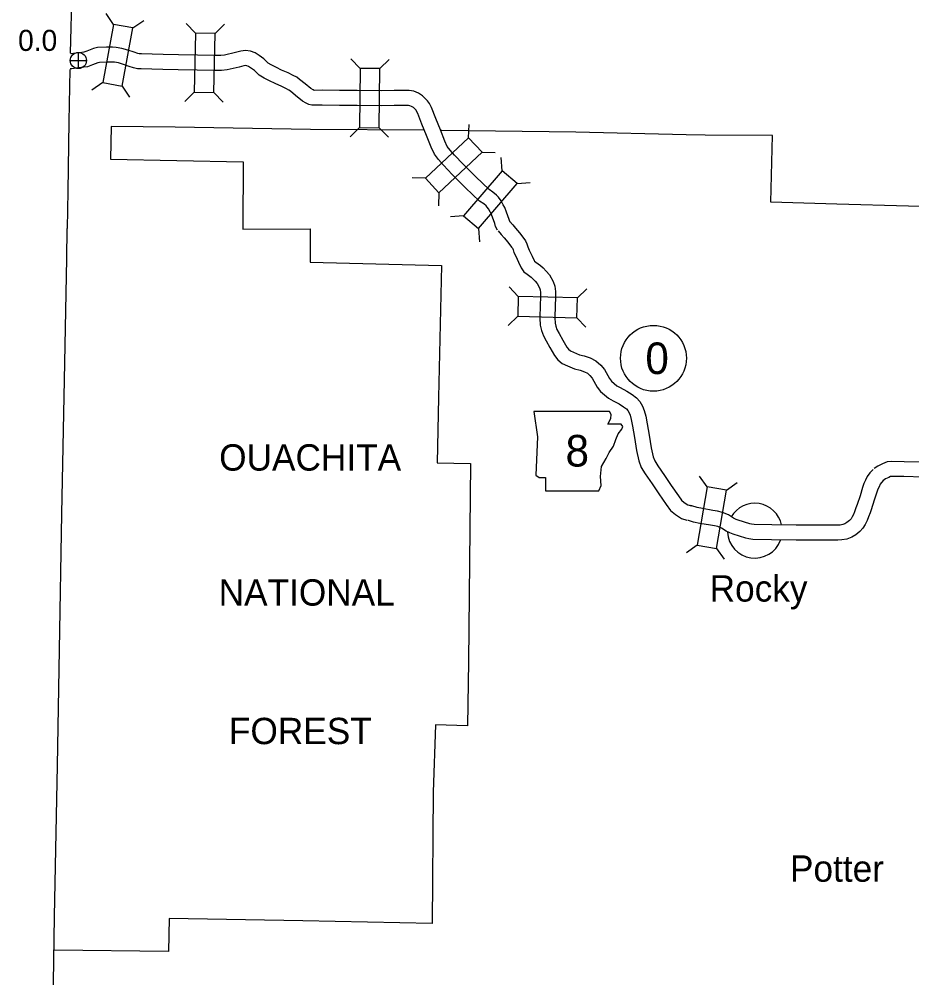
# Model space of a CAD drawing. Extents: x -939622 to -934245, y 1383184 to 1385301.
# Drawn here: x -936458.9 to -936405.2, y 1384124 to 1384181.7 of the extents above; entities that cross this region are included whole.
import ezdxf

# ---------------------------------------------------------------- set-up
doc = ezdxf.new("R2010")
doc.units = 0
for name, color, linetype in [('1', 7, 'Continuous'), ('10', 7, 'Continuous'), ('20', 7, 'Continuous'), ('21', 7, 'Continuous'), ('24', 7, 'Continuous'), ('25', 7, 'Continuous'), ('26', 7, 'Continuous'), ('27', 7, 'Continuous'), ('8', 7, 'Continuous')]:
    doc.layers.add(name, color=color, linetype=linetype)

msp = doc.modelspace()

# ---------------------------------------------------------------- linework, layer by layer
at = {"layer": '1'}
for points in [[(-936455.209, 1384206.003), (-936455.341, 1384199.965), (-936455.513, 1384191.445), (-936455.699, 1384183.522), (-936455.788, 1384179.641)], [(-936455.81, 1384178.662), (-936455.882, 1384175.54), (-936455.924, 1384171.353), (-936455.971, 1384169.096)], [(-936457.088, 1384106.667), (-936457.006, 1384111.46), (-936456.847, 1384119.738), (-936456.728, 1384127.705), (-936456.565, 1384136.797), (-936456.427, 1384143.745), (-936456.285, 1384151.935), (-936456.131, 1384159.99), (-936455.992, 1384167.281), (-936455.971, 1384169.096)]]:
    msp.add_lwpolyline(points, dxfattribs=at)
at = {"layer": '10'}
for points in [[(-936429.324, 1384169.483), (-936429.381, 1384169.574), (-936429.399, 1384169.646), (-936429.55, 1384170.086), (-936429.655, 1384170.363), (-936429.744, 1384170.521), (-936429.866, 1384170.758), (-936430.029, 1384170.976), (-936430.163, 1384171.113), (-936430.365, 1384171.286), (-936430.595, 1384171.451), (-936431.401, 1384172.198), (-936432.163, 1384172.968), (-936432.674, 1384173.512), (-936432.947, 1384173.812), (-936433.112, 1384174.039), (-936433.255, 1384174.343), (-936433.531, 1384175.03), (-936433.802, 1384175.711), (-936434.064, 1384176.384), (-936434.183, 1384176.62), (-936434.295, 1384176.788), (-936434.597, 1384177.089), (-936434.843, 1384177.236), (-936435.118, 1384177.358), (-936435.402, 1384177.393), (-936435.576, 1384177.392), (-936436.306, 1384177.393), (-936437.086, 1384177.387), (-936438.523, 1384177.403), (-936439.592, 1384177.405), (-936440.64, 1384177.411), (-936441.124, 1384177.409), (-936441.178, 1384177.438), (-936441.325, 1384177.515), (-936441.667, 1384177.792), (-936441.993, 1384178.072), (-936442.167, 1384178.197), (-936442.384, 1384178.307), (-936442.689, 1384178.455), (-936443.082, 1384178.628), (-936443.394, 1384178.792), (-936443.7, 1384178.94), (-936443.876, 1384179.05), (-936444.143, 1384179.3), (-936444.426, 1384179.503), (-936444.668, 1384179.668), (-936444.949, 1384179.758), (-936445.25, 1384179.807), (-936445.524, 1384179.769), (-936445.851, 1384179.681), (-936446.511, 1384179.525), (-936446.73, 1384179.502), (-936447.087, 1384179.504), (-936448.141, 1384179.524), (-936449.268, 1384179.553), (-936450.207, 1384179.574), (-936450.87, 1384179.59), (-936451.505, 1384179.602), (-936451.64, 1384179.604), (-936451.726, 1384179.623), (-936451.953, 1384179.705), (-936452.322, 1384179.829), (-936452.689, 1384179.932), (-936453.022, 1384179.994), (-936453.256, 1384180.011), (-936453.606, 1384180.004), (-936454.148, 1384179.982), (-936454.384, 1384179.933), (-936454.787, 1384179.774), (-936454.97, 1384179.704), (-936455.086, 1384179.689), (-936455.779, 1384179.606), (-936455.783, 1384179.606)], [(-936430.085, 1384169.002), (-936430.22, 1384169.217), (-936430.263, 1384169.391), (-936430.397, 1384169.78), (-936430.474, 1384169.983), (-936430.536, 1384170.095), (-936430.631, 1384170.278), (-936430.715, 1384170.389), (-936430.779, 1384170.456), (-936430.921, 1384170.577), (-936431.166, 1384170.753), (-936432.027, 1384171.551), (-936432.811, 1384172.343), (-936433.335, 1384172.901), (-936433.646, 1384173.243), (-936433.891, 1384173.579), (-936434.08, 1384173.984), (-936434.367, 1384174.695), (-936434.64, 1384175.382), (-936434.887, 1384176.018), (-936434.961, 1384176.166), (-936434.993, 1384176.213), (-936435.155, 1384176.374), (-936435.258, 1384176.436), (-936435.36, 1384176.481), (-936435.455, 1384176.493), (-936435.575, 1384176.492), (-936436.303, 1384176.493), (-936437.088, 1384176.487), (-936438.529, 1384176.503), (-936439.596, 1384176.505), (-936440.641, 1384176.511), (-936441.253, 1384176.509), (-936441.437, 1384176.558), (-936441.597, 1384176.641), (-936441.823, 1384176.76), (-936442.244, 1384177.1), (-936442.55, 1384177.364), (-936442.635, 1384177.425), (-936442.784, 1384177.5), (-936443.068, 1384177.638), (-936443.473, 1384177.817), (-936443.799, 1384177.988), (-936444.135, 1384178.15), (-936444.428, 1384178.333), (-936444.715, 1384178.603), (-936444.942, 1384178.766), (-936445.068, 1384178.851), (-936445.159, 1384178.88), (-936445.26, 1384178.897), (-936445.345, 1384178.885), (-936445.63, 1384178.809), (-936446.36, 1384178.635), (-936446.686, 1384178.602), (-936447.097, 1384178.604), (-936448.161, 1384178.624), (-936449.289, 1384178.653), (-936450.227, 1384178.674), (-936450.89, 1384178.69), (-936451.52, 1384178.703), (-936451.745, 1384178.705), (-936451.977, 1384178.757), (-936452.249, 1384178.854), (-936452.588, 1384178.969), (-936452.894, 1384179.055), (-936453.137, 1384179.1), (-936453.281, 1384179.111), (-936453.578, 1384179.104), (-936454.038, 1384179.086), (-936454.125, 1384179.068), (-936454.46, 1384178.936), (-936454.749, 1384178.824), (-936454.976, 1384178.796), (-936455.686, 1384178.711), (-936455.802, 1384178.701)], [(-936429.363, 1384169.535), (-936429.179, 1384169.321), (-936429.009, 1384169.121), (-936428.773, 1384168.843), (-936428.514, 1384168.503), (-936428.417, 1384168.355), (-936428.328, 1384168.174), (-936428.264, 1384167.992), (-936428.18, 1384167.802), (-936428.014, 1384167.445), (-936427.887, 1384167.173), (-936427.86, 1384167.133), (-936427.781, 1384167.076), (-936427.5, 1384166.871), (-936427.352, 1384166.736), (-936427.163, 1384166.537), (-936426.97, 1384166.304), (-936426.753, 1384165.919), (-936426.646, 1384165.635), (-936426.603, 1384165.313), (-936426.606, 1384164.927), (-936426.632, 1384164.475), (-936426.65, 1384163.72), (-936426.634, 1384163.402), (-936426.594, 1384163.228), (-936426.516, 1384163.024), (-936426.376, 1384162.781), (-936426.155, 1384162.375), (-936425.925, 1384161.965), (-936425.821, 1384161.838), (-936425.712, 1384161.746), (-936425.513, 1384161.653), (-936425.171, 1384161.506), (-936424.885, 1384161.436), (-936424.516, 1384161.317), (-936424.17, 1384161.134), (-936423.886, 1384160.878), (-936423.664, 1384160.608), (-936423.358, 1384160.074), (-936423.231, 1384159.916), (-936423.068, 1384159.766), (-936422.923, 1384159.641), (-936422.709, 1384159.535), (-936422.315, 1384159.317), (-936422.002, 1384159.106), (-936421.735, 1384158.912), (-936421.533, 1384158.684), (-936421.375, 1384158.421), (-936421.265, 1384158.151), (-936421.172, 1384157.813), (-936421.089, 1384157.359), (-936420.974, 1384156.676), (-936420.848, 1384155.902), (-936420.734, 1384155.37), (-936420.641, 1384155.121), (-936420.46, 1384154.824), (-936420.059, 1384154.244), (-936419.648, 1384153.649), (-936419.208, 1384153.01), (-936419.023, 1384152.758), (-936418.861, 1384152.623), (-936418.643, 1384152.48), (-936418.432, 1384152.411)], [(-936430.046, 1384168.95), (-936429.864, 1384168.737), (-936429.695, 1384168.538), (-936429.475, 1384168.279), (-936429.248, 1384167.981), (-936429.2, 1384167.908), (-936429.159, 1384167.825), (-936429.101, 1384167.66), (-936429, 1384167.431), (-936428.83, 1384167.065), (-936428.674, 1384166.732), (-936428.519, 1384166.497), (-936428.308, 1384166.347), (-936428.07, 1384166.172), (-936427.982, 1384166.093), (-936427.837, 1384165.94), (-936427.715, 1384165.792), (-936427.571, 1384165.537), (-936427.524, 1384165.413), (-936427.503, 1384165.256), (-936427.506, 1384164.956), (-936427.531, 1384164.512), (-936427.551, 1384163.709), (-936427.529, 1384163.277), (-936427.457, 1384162.965), (-936427.332, 1384162.636), (-936427.161, 1384162.34), (-936426.942, 1384161.939), (-936426.672, 1384161.458), (-936426.466, 1384161.204), (-936426.2, 1384160.981), (-936425.881, 1384160.832), (-936425.458, 1384160.65), (-936425.131, 1384160.57), (-936424.868, 1384160.485), (-936424.69, 1384160.391), (-936424.539, 1384160.255), (-936424.408, 1384160.095), (-936424.104, 1384159.565), (-936423.891, 1384159.3), (-936423.667, 1384159.093), (-936423.424, 1384158.885), (-936423.127, 1384158.738), (-936422.785, 1384158.549), (-936422.518, 1384158.368), (-936422.344, 1384158.242), (-936422.261, 1384158.149), (-936422.182, 1384158.017), (-936422.119, 1384157.862), (-936422.05, 1384157.612), (-936421.975, 1384157.202), (-936421.862, 1384156.529), (-936421.732, 1384155.736), (-936421.601, 1384155.117), (-936421.454, 1384154.724), (-936421.214, 1384154.334), (-936420.8, 1384153.732), (-936420.389, 1384153.138), (-936419.941, 1384152.488), (-936419.683, 1384152.137), (-936419.398, 1384151.898), (-936419.036, 1384151.662), (-936418.711, 1384151.556)], [(-936404.488, 1384155.051), (-936405.634, 1384155.073), (-936406.401, 1384155.084), (-936406.662, 1384155.064), (-936406.943, 1384154.95), (-936407.224, 1384154.804), (-936407.436, 1384154.656)], [(-936407.5, 1384154.602), (-936407.697, 1384154.4), (-936407.852, 1384154.172), (-936407.96, 1384153.956), (-936408.053, 1384153.756), (-936408.134, 1384153.527), (-936408.29, 1384153.024), (-936408.463, 1384152.488), (-936408.534, 1384152.304), (-936408.619, 1384152.057), (-936408.681, 1384151.898), (-936408.757, 1384151.748), (-936408.828, 1384151.64), (-936408.925, 1384151.535), (-936409.075, 1384151.412), (-936409.195, 1384151.337), (-936409.323, 1384151.289), (-936409.481, 1384151.262), (-936409.656, 1384151.25), (-936410.04, 1384151.249), (-936412.124, 1384151.25), (-936413.593, 1384151.279), (-936414.664, 1384151.289), (-936414.812, 1384151.309), (-936414.924, 1384151.338), (-936415.626, 1384151.554), (-936415.739, 1384151.6), (-936415.894, 1384151.681), (-936416.21, 1384151.873), (-936416.552, 1384152.02), (-936416.866, 1384152.1), (-936417.138, 1384152.146), (-936417.761, 1384152.247), (-936418.085, 1384152.31), (-936418.398, 1384152.411), (-936418.498, 1384152.427)], [(-936406.857, 1384153.972), (-936406.998, 1384153.828), (-936407.074, 1384153.717), (-936407.149, 1384153.565), (-936407.22, 1384153.414), (-936407.279, 1384153.245), (-936407.432, 1384152.753), (-936407.614, 1384152.186), (-936407.689, 1384151.995), (-936407.774, 1384151.747), (-936407.858, 1384151.532), (-936407.977, 1384151.295), (-936408.118, 1384151.083), (-936408.306, 1384150.879), (-936408.55, 1384150.679), (-936408.793, 1384150.528), (-936409.084, 1384150.416), (-936409.375, 1384150.367), (-936409.626, 1384150.35), (-936410.04, 1384150.349), (-936412.133, 1384150.35), (-936413.606, 1384150.379), (-936414.731, 1384150.389), (-936414.986, 1384150.425), (-936415.168, 1384150.472), (-936415.929, 1384150.705), (-936416.118, 1384150.783), (-936416.336, 1384150.896), (-936416.624, 1384151.071), (-936416.843, 1384151.165), (-936417.052, 1384151.219), (-936417.285, 1384151.258), (-936417.918, 1384151.361), (-936418.31, 1384151.436), (-936418.611, 1384151.534), (-936418.645, 1384151.539)], [(-936404.515, 1384154.151), (-936405.65, 1384154.173), (-936406.372, 1384154.184), (-936406.452, 1384154.177), (-936406.566, 1384154.131), (-936406.757, 1384154.032), (-936406.921, 1384153.918)]]:
    msp.add_lwpolyline(points, dxfattribs=at)
at = {"layer": '20'}
for p, q in [((-936453.188, 1384181.379), (-936453.637, 1384182.031)), ((-936452.02, 1384181.163), (-936451.367, 1384181.613)), ((-936448.263, 1384180.859), (-936448.812, 1384181.429)), ((-936447.075, 1384180.836), (-936446.505, 1384181.385)), ((-936438.357, 1384178.733), (-936438.91, 1384179.3)), ((-936437.169, 1384178.72), (-936436.602, 1384179.274)), ((-936453.834, 1384177.874), (-936454.486, 1384177.424)), ((-936452.666, 1384177.658), (-936452.216, 1384177.006)), ((-936448.332, 1384177.295), (-936448.902, 1384176.746)), ((-936447.144, 1384177.272), (-936446.595, 1384176.702)), ((-936438.396, 1384175.17), (-936438.962, 1384174.616)), ((-936437.208, 1384175.156), (-936436.654, 1384174.59)), ((-936431.832, 1384174.561), (-936431.807, 1384175.353)), ((-936431.018, 1384173.695), (-936430.227, 1384173.67)), ((-936429.82, 1384172.572), (-936429.881, 1384173.362)), ((-936434.43, 1384172.121), (-936435.221, 1384172.146)), ((-936428.917, 1384171.8), (-936428.127, 1384171.861)), ((-936433.616, 1384171.255), (-936433.641, 1384170.464)), ((-936432.137, 1384169.864), (-936432.926, 1384169.802)), ((-936431.234, 1384169.092), (-936431.172, 1384168.302)), ((-936428.851, 1384165.008), (-936429.397, 1384165.582)), ((-936425.288, 1384164.92), (-936424.714, 1384165.466)), ((-936428.88, 1384163.82), (-936429.454, 1384163.274)), ((-936425.318, 1384163.732), (-936424.772, 1384163.158)), ((-936417.49, 1384153.556), (-936417.949, 1384154.202)), ((-936416.319, 1384153.358), (-936415.673, 1384153.817)), ((-936418.084, 1384150.042), (-936418.73, 1384149.583)), ((-936416.913, 1384149.844), (-936416.454, 1384149.199))]:
    msp.add_line(p, q, dxfattribs=at)
for points in [[(-936453.188, 1384181.379), (-936453.834, 1384177.874), (-936452.666, 1384177.658), (-936452.02, 1384181.163)], [(-936447.144, 1384177.272), (-936447.075, 1384180.836), (-936448.263, 1384180.859), (-936448.332, 1384177.295)], [(-936438.357, 1384178.733), (-936438.396, 1384175.17), (-936437.208, 1384175.156), (-936437.169, 1384178.72)], [(-936431.832, 1384174.561), (-936434.43, 1384172.121), (-936433.616, 1384171.255), (-936431.018, 1384173.695)], [(-936429.82, 1384172.572), (-936432.137, 1384169.864), (-936431.234, 1384169.092), (-936428.917, 1384171.8)], [(-936428.88, 1384163.82), (-936425.318, 1384163.732), (-936425.288, 1384164.92), (-936428.851, 1384165.008)], [(-936416.913, 1384149.844), (-936416.319, 1384153.358), (-936417.49, 1384153.556), (-936418.084, 1384150.042)]]:
    msp.add_lwpolyline(points, close=True, dxfattribs=at)
at = {"layer": '21'}
msp.add_lwpolyline([(-936427.917, 1384158.085), (-936427.689, 1384156.563), (-936427.79, 1384154.254), (-936427.587, 1384154.127), (-936427.207, 1384154.127), (-936427.207, 1384153.315), (-936424.009, 1384153.315), (-936423.857, 1384153.644), (-936423.908, 1384154.177), (-936423.832, 1384154.786), (-936423.552, 1384155.269), (-936423.375, 1384155.624), (-936423.121, 1384156.005), (-936422.969, 1384156.411), (-936422.842, 1384156.74), (-936422.613, 1384157.02), (-936422.563, 1384157.197), (-936422.664, 1384157.324), (-936423.451, 1384157.324), (-936423.273, 1384157.679), (-936423.248, 1384157.908), (-936423.353, 1384158.083)], close=True, dxfattribs=at)
at = {"layer": '24'}
for start, end in [(12.50024, 149.6927), (183.08042, 339.67969)]:
    msp.add_arc((-936414.617, 1384150.921), 1.65, start, end, dxfattribs=at)
at = {"layer": '26'}
for p, q in [((-936455.786, 1384179.204), (-936454.811, 1384179.204)), ((-936455.299, 1384178.717), (-936455.299, 1384179.692))]:
    msp.add_line(p, q, dxfattribs=at)
msp.add_circle((-936455.299, 1384179.204), 0.487, dxfattribs=at)
at = {"layer": '27'}
msp.add_circle((-936420.715, 1384161.294), 1.98, dxfattribs=at)
at = {"layer": '8'}
for points in [[(-936434.512, 1384175.005), (-936441.345, 1384175.056), (-936449.478, 1384175.199), (-936453.332, 1384175.245), (-936453.37, 1384173.262), (-936445.395, 1384173.1), (-936445.415, 1384169.166)], [(-936418.745, 1384174.734), (-936425.378, 1384174.896), (-936433.446, 1384174.996), (-936433.518, 1384174.997)], [(-936401.095, 1384169.442), (-936401.071, 1384170.316), (-936409.692, 1384170.569), (-936413.645, 1384170.692), (-936413.545, 1384174.689), (-936417.603, 1384174.712), (-936418.745, 1384174.734)], [(-936445.415, 1384169.166), (-936445.402, 1384169.068), (-936441.351, 1384169.076), (-936441.364, 1384167.074), (-936433.461, 1384166.864), (-936433.65, 1384158.929), (-936433.731, 1384155), (-936431.71, 1384154.969), (-936431.764, 1384151.018), (-936431.842, 1384143.054), (-936431.891, 1384139.191), (-936433.822, 1384139.247), (-936433.965, 1384135.187), (-936434.017, 1384127.29), (-936441.805, 1384127.458), (-936449.83, 1384127.594), (-936449.871, 1384125.6), (-936456.758, 1384125.695)]]:
    msp.add_lwpolyline(points, dxfattribs=at)

# ---------------------------------------------------------------- texts
at = {"layer": '21'}
msp.add_text('8', height=1.901, dxfattribs=at).set_placement((-936426.002, 1384154.781))
at = {"layer": '24'}
for s, p in [('Rocky', (-936417.335, 1384146.657)), ('Potter', (-936412.504, 1384129.805))]:
    msp.add_text(s, height=1.584, dxfattribs=at).set_placement(p)
at = {"layer": '25'}
msp.add_text('0.0', height=1.2672, dxfattribs=at).set_placement((-936458.926, 1384179.782))
at = {"layer": '27'}
msp.add_text('0', height=1.901, dxfattribs=at).set_placement((-936421.199, 1384160.343))
at = {"layer": '8'}
for s, p in [('OUACHITA', (-936446.832, 1384154.535)), ('NATIONAL', (-936446.864, 1384146.415)), ('FOREST', (-936446.245, 1384138.081))]:
    msp.add_text(s, height=1.584, dxfattribs=at).set_placement(p)

doc.saveas('drawing.dxf')
